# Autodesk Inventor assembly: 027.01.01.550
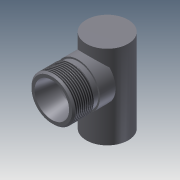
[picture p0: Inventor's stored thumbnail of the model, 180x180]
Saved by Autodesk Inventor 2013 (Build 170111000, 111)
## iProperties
Shininess: 64.0
Length Units: 11269
Angle Units: 11279
Time Units: 11290
Mass Units: 11283
Length Display Precision: 3
Angle Display Precision: 2
Compacted: True
Created: 2004-12
Part Number: 027.01.01.550
Document SubType Name: Assembly
Designer: ELarisa
Manufacturer: Standard
Standards Organization: Custom
Density: 0.0
Volumn: 0.0
Area: 0.0
PropertySet Name: Model Information
Control State: 0
Master: False
Checked Out: False
Checked Out Date: 2008-10-15
Last Check In Date: 2008-10-15
Author: ELarisa
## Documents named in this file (3)
- D:\FrontLoaderVault\Data\Assy, Chassis, Front\027.01.01.550.iam
- D:\FrontLoaderVault\Data\Assy, Chassis, Front\027.02.01.012.ipt
- D:\FrontLoaderVault\Data\Assy, Chassis, Front\027.03.08.267.ipt
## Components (2 placed, 2 different names)
1. 027.02.01.012:1 — Mate:1, Tangent:1
2. 027.03.08.267:1 — Mate:1, Tangent:1
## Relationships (2: Mate 1, Tangent 1)
- Mate:1: 027.02.01.012:1 ↔ 027.03.08.267:1
- Tangent:1: 027.02.01.012:1 ↔ 027.03.08.267:1
